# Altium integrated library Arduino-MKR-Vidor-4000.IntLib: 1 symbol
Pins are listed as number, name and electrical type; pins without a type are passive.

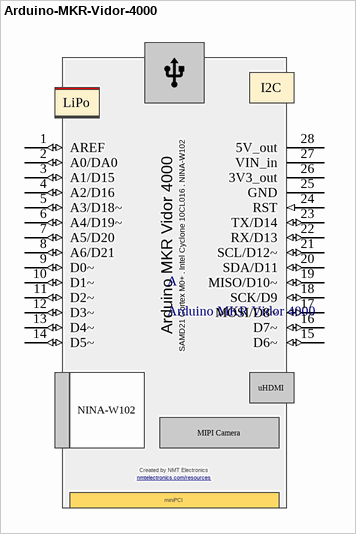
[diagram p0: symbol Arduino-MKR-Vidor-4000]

## Arduino-MKR-Vidor-4000
designator A, comment Arduino MKR Vidor 4000
Arduino Board with SAMD21 Cortex M0+, Intel Cyclone 10CL1016 FPGA, and NINA-W102 Radio Module; NMT Release: B210422
footprint Arduino-MKR-Vidor-4000-THT (No Headers)
footprint Arduino-MKR-Vidor-4000-THT (On Headers)
pins: 1 AREF (io), 2 A0/DA0 (io), 3 A1/D15 (io), 4 A2/D16 (io), 5 A3/D18~ (io), 6 A4/D19~ (io), 7 A5/D20 (io), 8 A6/D21 (io), 9 D0~ (io), 10 D1~ (io), 11 D2~ (io), 12 D3~ (io), 13 D4~ (io), 14 D5~ (io), 15 D6~ (io), 16 D7~ (io), 17 MOSI/D8~ (io), 18 SCK/D9 (io), 19 MISO/D10~ (io), 20 SDA/D11 (io), 21 SCL/D12~ (io), 22 RX/D13 (io), 23 TX/D14 (io), 24 RST (in), 25 GND (power), 26 3V3_out (power), 27 VIN_in (power), 28 5V_out (power)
